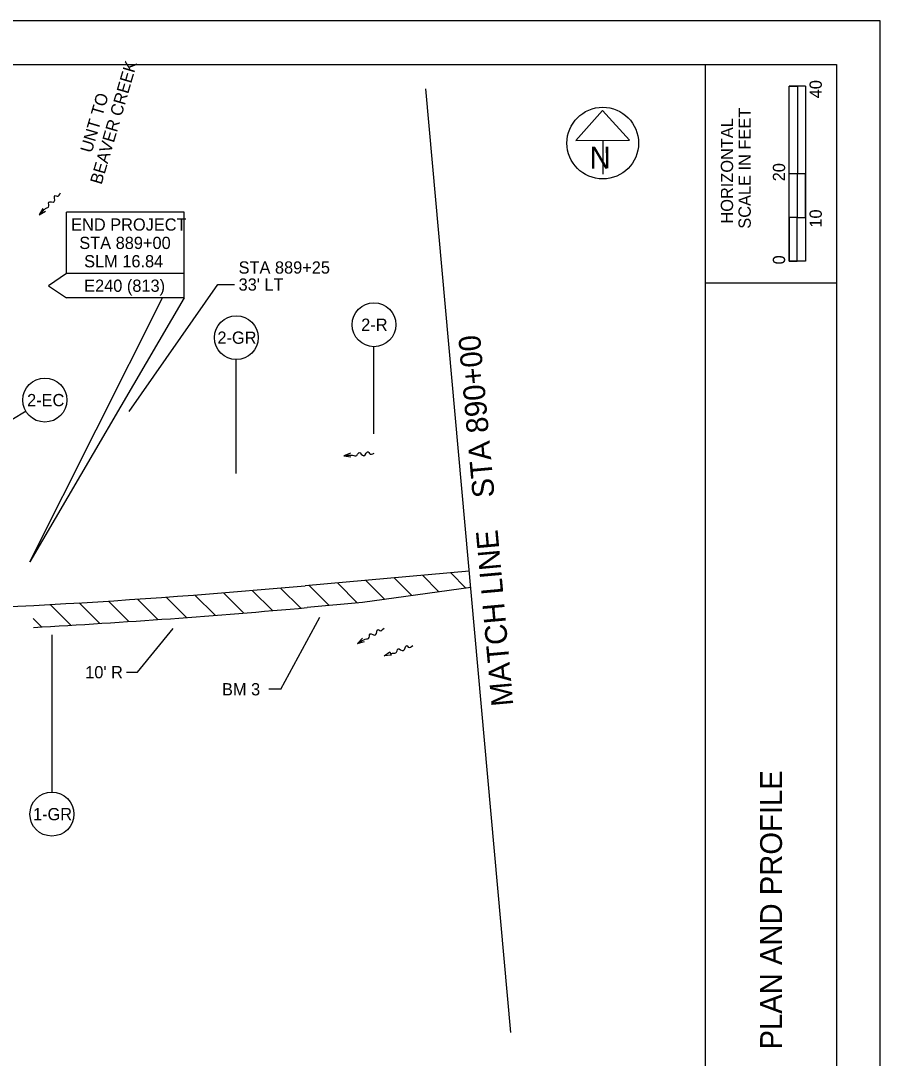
# Model space of a CAD drawing. Extents: x 0 to 2520, y -440 to 502.
# Drawn here: x 483.2 to 680, y 202.5 to 440 of the extents above; entities that cross this region are included whole.
import ezdxf

# ---------------------------------------------------------------- set-up
doc = ezdxf.new("R2010")
doc.units = 0
for name, color, linetype in [('DR_X_Culvert', 7, 'Continuous'), ('MT_P_Edge_Line', 7, 'Continuous'), ('MT_P_Temp_Road', 7, 'Continuous'), ('MT_P_Transverse_Line', 7, 'Continuous'), ('PF_P_Grade_Line', 7, 'Continuous'), ('PF_X_Ground_Line', 7, 'Continuous'), ('PV_P_Shoulder', 7, 'Continuous'), ('SC_Scratch1', 7, 'Continuous'), ('TX_P_1', 7, 'Continuous'), ('XS_P_Pavt_Surface', 7, 'Continuous')]:
    doc.layers.add(name, color=color, linetype=linetype)

msp = doc.modelspace()

# ---------------------------------------------------------------- linework, layer by layer
at = {"layer": 'DR_X_Culvert'}
msp.add_lwpolyline([(0, 0), (680, 0), (680, 440), (0, 440)], close=True, dxfattribs=at)
at = {"layer": 'MT_P_Edge_Line'}
for p, q in [((564.09, 345.42), (564.09, 365.41)), ((532.57, 336.35), (532.57, 362.45)), ((484.42, 350.61), (471.03, 342.63)), ((490.34, 299.45), (490.34, 263.45))]:
    msp.add_line(p, q, dxfattribs=at)
at = {"layer": 'MT_P_Temp_Road'}
for p, q in [((585.9, 314.05), (548.33, 310.66)), ((581.65, 313.66), (585.15, 310.16)), ((555.7, 311.33), (560.31, 306.72)), ((562.19, 311.91), (566.56, 307.54)), ((568.68, 312.5), (572.76, 308.42)), ((575.16, 313.08), (578.95, 309.29)), ((529.66, 309.08), (534.3, 304.44)), ((536.2, 309.61), (540.83, 304.99)), ((542.72, 310.17), (547.33, 305.55)), ((549.21, 310.74), (553.82, 306.14)), ((586.23, 310.31), (561.45, 306.82)), ((489.94, 306.38), (494.67, 301.65)), ((496.62, 306.77), (501.34, 302.05)), ((503.27, 307.19), (507.98, 302.48)), ((509.91, 307.63), (514.59, 302.94)), ((516.51, 308.09), (521.19, 303.42)), ((523.1, 308.57), (527.76, 303.92)), ((561.45, 306.82), (548.78, 305.68)), ((486.02, 303.23), (487.98, 301.26))]:
    msp.add_line(p, q, dxfattribs=at)
for radius, start in [(1760.76, 267.51735), (1765.76, 273.10867)]:
    msp.add_arc((390.37, 2064.33), radius, start, 275.14679, dxfattribs=at)
at = {"layer": 'MT_P_Transverse_Line'}
for p, q in [((488.25, 397.05), (487.45, 395.6)), ((487.45, 395.6), (488.87, 396.45)), ((558.72, 341.02), (557.16, 340.46)), ((557.16, 340.46), (558.79, 340.16)), ((561.49, 298.66), (560.32, 297.49)), ((560.32, 297.49), (561.92, 297.91))]:
    msp.add_line(p, q, dxfattribs=at)
for points in [[(487.45, 395.6), (488.61, 396.79), (489.17, 397.16), (489.57, 397.36), (489.62, 398.48), (490.89, 398.61), (491.07, 399.99), (491.55, 399.84), (492.3, 400.64)], [(557.16, 340.46), (558.82, 340.59), (559.49, 340.5), (559.91, 340.39), (560.7, 341.19), (561.73, 340.45), (562.78, 341.37), (563.04, 340.94), (564.14, 341.04)], [(560.32, 297.49), (561.76, 298.31), (562.4, 298.51), (562.84, 298.6), (563.2, 299.66), (564.46, 299.43), (565.01, 300.7), (565.43, 300.43), (566.38, 300.99)]]:
    msp.add_spline(points, degree=3, dxfattribs=at)
at = {"layer": 'PF_P_Grade_Line'}
for p, q in [((595.41, 208.45), (575.96, 424.39)), ((493.66, 382.16), (493.66, 396.16)), ((520.66, 396.16), (493.66, 396.16)), ((520.66, 376.56), (520.66, 396.16)), ((520.66, 382.16), (493.66, 382.16)), ((508.01, 350.6), (528.31, 379.63)), ((528.31, 379.63), (532.17, 379.63)), ((520.66, 376.56), (493.66, 376.56)), ((542.74, 287), (551.67, 303.49)), ((509.93, 290.91), (518.09, 300.91)), ((507.4, 290.91), (509.93, 290.91)), ((542.74, 287), (539.99, 287))]:
    msp.add_line(p, q, dxfattribs=at)
for points in [[(493.66, 382.16), (489.56, 379.36), (493.66, 376.56)], [(520.66, 376.56), (485.32, 316.14), (515.7, 376.56)]]:
    msp.add_lwpolyline(points, dxfattribs=at)
for centre in [(564.09, 370.43), (532.57, 367.47), (488.73, 353.18), (490.34, 258.42)]:
    msp.add_circle(centre, 5.03, dxfattribs=at)
at = {"layer": 'PF_X_Ground_Line'}
for p, q in [((659.13, 385), (659.13, 425)), ((662.88, 425), (659.13, 425)), ((659.13, 405), (659.13, 425)), ((659.13, 425), (661, 425)), ((661, 425), (661.02, 425)), ((661.02, 425), (661.02, 405)), ((662.88, 425), (662.88, 385)), ((661.02, 405), (659.13, 405)), ((662.87, 405), (661, 405)), ((661, 405), (661, 395)), ((662.87, 395), (662.87, 405)), ((661, 395), (659.13, 395)), ((659.13, 395), (659.13, 385)), ((661, 385), (661, 395)), ((661, 395), (662.87, 395)), ((662.88, 385), (659.13, 385)), ((659.13, 385), (661, 385))]:
    msp.add_line(p, q, dxfattribs=at)
at = {"layer": 'PV_P_Shoulder'}
msp.add_circle((616.46, 412), 8.2, dxfattribs=at)
at = {"layer": 'SC_Scratch1'}
for p, q in [((616.41, 419.48), (610.3, 412.62)), ((622.6, 412.69), (616.41, 419.48)), ((610.3, 412.62), (622.6, 412.69)), ((616.45, 412.65), (616.5, 404.92))]:
    msp.add_line(p, q, dxfattribs=at)
msp.add_circle((616.46, 412), 8.2, dxfattribs=at)
at = {"layer": 'TX_P_1'}
for p, q in [((640, 10), (640, 430)), ((640, 380), (670, 380))]:
    msp.add_line(p, q, dxfattribs=at)
msp.add_lwpolyline([(30, 430), (670, 430), (670, 10), (30, 10)], close=True, dxfattribs=at)
at = {"layer": 'XS_P_Pavt_Surface'}
for p, q in [((566.39, 294.64), (567.75, 295.59)), ((568.04, 294.79), (566.39, 294.64)), ((567.75, 295.59), (568.04, 294.79))]:
    msp.add_line(p, q, dxfattribs=at)
msp.add_spline([(567.9, 295.18), (567.96, 295.21), (568.63, 295.29), (569.07, 295.3), (569.61, 296.28), (570.81, 295.84), (571.58, 296.99), (571.94, 296.65), (572.97, 297.04)], degree=3, dxfattribs=at)

# ---------------------------------------------------------------- texts
at = {"layer": 'MT_P_Edge_Line'}
for s, p in [('BEAVER CREEK', (501.71, 402.36)), ('UNT TO', (499.45, 409.59))]:
    msp.add_text(s, height=2.8, rotation=73.695, dxfattribs=at).set_placement(p)
at = {"layer": 'PF_P_Grade_Line'}
for s, p in [('END PROJECT', (494.75, 391.96)), ('STA 889+00', (496.62, 387.76)), ('SLM 16.84', (497.72, 383.56)), ('STA 889+25', (533.09, 382.13)), ('E240 (813)', (497.73, 377.96)), ("33' LT", (533.09, 378.23)), ('2-R', (561.16, 369.03)), ('2-GR', (528.24, 366.07)), ('2-EC', (484.66, 351.78)), ("10' R", (497.97, 289.51)), ('BM 3', (529.29, 285.6)), ('1-GR', (486.02, 257.02))]:
    msp.add_text(s, height=2.8, dxfattribs=at).set_placement(p)
at = {"layer": 'PF_X_Ground_Line'}
for s, height, rotation, p in [('40', 2.8, 90, (666.61, 422.25)), ('SCALE IN FEET', 2.8, 90, (650.35, 392.41)), ('HORIZONTAL', 2.8, 90, (646.3, 393.58)), ('20', 2.8, 90, (658.21, 403.25)), ('10', 2.8, 90, (666.61, 392.65)), ('0', 2.8, 90, (658.21, 384.23)), ('MATCH LINE    STA 890+00', 5, 95.1468, (596.01, 283.32)), ('PLAN AND PROFILE', 5, 90, (657.5, 204.55))]:
    msp.add_text(s, height=height, rotation=rotation, dxfattribs=at).set_placement(p)
at = {"layer": 'SC_Scratch1'}
msp.add_text('N', height=5, rotation=0.3556, dxfattribs=at).set_placement((613.47, 406.16))

doc.saveas('drawing.dxf')
